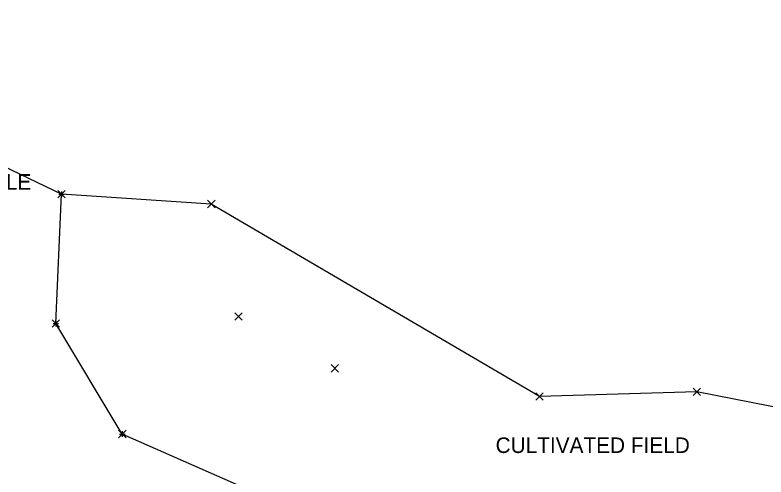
# Model space of a CAD drawing. Extents: x 211013 to 211654, y 505587 to 505872.
# Drawn here: x 211376.6 to 211511.7, y 505788.3 to 505871.5 of the extents above; entities that cross this region are included whole.
import ezdxf

# ---------------------------------------------------------------- set-up
doc = ezdxf.new("R2010")
doc.units = 0
for name, color, linetype in [('DV_X_Section_VMS_Line', 7, 'Continuous'), ('GE_X_Alignment', 7, 'Continuous'), ('RW_X_Esmt_SH', 7, 'Continuous'), ('SV_X_Terrain_Boundary', 7, 'Continuous'), ('SV_X_Text', 7, 'Continuous'), ('VG_X_Text', 7, 'Continuous')]:
    doc.layers.add(name, color=color, linetype=linetype)

msp = doc.modelspace()

# ---------------------------------------------------------------- linework, layer by layer
at = {"layer": 'DV_X_Section_VMS_Line'}
for p, q in [((211384.44, 505839.21), (211385.44, 505839.21)), ((211384.94, 505839.71), (211384.94, 505838.71)), ((211384.94, 505839.21), (211384.94, 505839.21)), ((211383.42, 505815.91), (211384.42, 505815.91)), ((211383.92, 505816.41), (211383.92, 505815.41)), ((211383.92, 505815.91), (211383.92, 505815.91)), ((211395.38, 505796.03), (211396.38, 505796.03)), ((211395.88, 505796.53), (211395.88, 505795.53)), ((211395.88, 505796.03), (211395.88, 505796.03))]:
    msp.add_line(p, q, dxfattribs=at)
at = {"layer": 'GE_X_Alignment'}
msp.add_lwpolyline([(211647.11, 505766.88), (211605.18, 505766.94), (211562.5, 505771.87), (211523.74, 505777.96), (211494.97, 505782.5), (211454.68, 505783.13), (211428.41, 505781.64), (211395.88, 505796.03), (211383.92, 505815.91), (211384.94, 505839.21)], dxfattribs=at)
at = {"layer": 'RW_X_Esmt_SH'}
for p, q in [((211384.27, 505838.54), (211385.61, 505839.88)), ((211384.27, 505839.88), (211385.61, 505838.54)), ((211411.24, 505836.76), (211412.57, 505838.1)), ((211411.24, 505838.1), (211412.57, 505836.76)), ((211416.11, 505816.5), (211417.44, 505817.83)), ((211416.11, 505817.83), (211417.44, 505816.5)), ((211383.26, 505815.25), (211384.59, 505816.58)), ((211383.26, 505816.58), (211384.59, 505815.25)), ((211433.48, 505807.19), (211434.82, 505808.53)), ((211433.48, 505808.53), (211434.82, 505807.19)), ((211498.62, 505802.98), (211499.96, 505804.31)), ((211498.62, 505804.31), (211499.96, 505802.98)), ((211470.31, 505802.14), (211471.64, 505803.47)), ((211470.31, 505803.47), (211471.64, 505802.14)), ((211395.22, 505795.36), (211396.55, 505796.7)), ((211395.22, 505796.7), (211396.55, 505795.36))]:
    msp.add_line(p, q, dxfattribs=at)
at = {"layer": 'SV_X_Terrain_Boundary'}
msp.add_lwpolyline([(211525.59, 505798.45), (211499.29, 505803.64), (211470.97, 505802.81), (211411.9, 505837.43), (211384.94, 505839.21), (211371.51, 505845.61), (211359.91, 505852.08), (211358.55, 505853.68), (211356.76, 505857.01), (211351.82, 505854.45), (211348.82, 505855.06), (211308.23, 505871.46), (211291.29, 505855.96), (211275.17, 505843.44), (211270.14, 505834.75), (211258.57, 505812.76), (211238.01, 505789.67)], dxfattribs=at)

# ---------------------------------------------------------------- texts
at = {"layer": 'SV_X_Text'}
msp.add_text('CULTIVATED FIELD', height=2.8, dxfattribs=at).set_placement((211463.07, 505792.62))
at = {"layer": 'VG_X_Text'}
msp.add_text('10" TRIPLE', height=2.8, dxfattribs=at).set_placement((211359.86, 505840.02))

doc.saveas('drawing.dxf')
